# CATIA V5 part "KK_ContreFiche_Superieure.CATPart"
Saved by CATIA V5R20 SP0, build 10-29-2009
Part number: Contre fiche superieure
Bounding box of the stored display mesh (mm): x -2149.211 to -734.695, y 594.809 to 1312.939, z -1095.218 to -192.003
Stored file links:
  G:\Khaled_CFAO_2011\ST2M\ST2M_GR2\aboulegue\Khaled\CAD_thinkMOTION\KK_ContreFiche_Superieure.CATPart
  G:\Khaled_CFAO_2011\ST2M\ST2M_GR2\aboulegue\Khaled\CAD_thinkMOTION\KK_Train_Atterrissage.CATProduct
  G:\Khaled_CFAO_2011\ST2M\ST2M_GR2\aboulegue\CFAO_aboulegue\CFAO_aboulegue_fichiers_catia\Squelette_tige_verin_deverouillage.CATPart
  G:\Khaled_CFAO_2011\ST2M\ST2M_GR2\aboulegue\Khaled\CAD_thinkMOTION\KK_SqueletteContre_Friche.CATPart
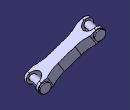
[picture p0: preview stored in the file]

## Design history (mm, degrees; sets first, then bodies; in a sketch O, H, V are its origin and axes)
External parameters (linked from other documents)
  `External.Longueur contre fiche superieure` = 1280 mm
Set1
  Plane1 "Plan reference contre fiche superieue": linked copy from another document
  Point1 "Point.15": linked copy from another document
  Point2 "Point.12": linked copy from another document
  Line1: linked copy from another document
  Point3 "Point.28": linked copy from another document
Body1 (main body)
  Sketch1 on Plane1, origin (95.3692, 652.5403, 0), H (0.9817, -0.1905, 0), V (0, 0, 1)
    construction line L1 (-2118.1492, -320) -> (-1013.8369, -967.2204)
    point P1 (-2118.1492, -320)
    point P2 (-1013.8369, -967.2204)
    line L2 (-2053.4272, -209.5688) -> (-949.1148, -856.7891)
    line L3 (-1078.5589, -1077.6516) -> (-2182.8713, -430.4312)
    arc A1 centre (-1013.8369, -967.2204) radius 128 from (-949.1148, -856.7891) to (-1078.5589, -1077.6516) cw
    arc A2 centre (-2118.1492, -320) radius 128 from (-2182.8713, -430.4312) to (-2053.4272, -209.5688) cw
    reference projected point E1 (-1013.8369, -967.2204) from Point1
    reference projected point E2 (-2118.1492, -320) from Point2
    distance L1 L2 = 128 {= 128mm*(`External.Longueur contre fiche superieure` /1280mm)}
    tangency: A1 L2, A2 L2, A1 L3, A2 L3
    coincidence: P2 E1, P1 E2
  Pad1: profile Sketch1, direction (-0.1905, -0.9817, 0), length 208 {= 208mm*(`External.Longueur contre fiche superieure` /1280mm)}, mirrored extent
  Sketch2 on face of Pad1 from Sketch1.L2, origin (-620.982, 92.7993, -1063.3821), H (0.1586, 0.9872, 0.0189), V (-0.8535, 0.1274, 0.5053)
    construction line L1 (9.8704, 1048.9435) -> (1379.4914, 997.579)
    reference projected line E1 (748.7259, 1661.2666) -> (700.7562, 382.1658) from Line1
    reference projected point E2 (724.7567, 1022.1333) from Point3
    point P3 (580.8578, 1027.5299)
    line L2 (580.8578, 1027.5299) -> (573.3626, 827.6704)
    arc A1 centre (-161.246, 855.2202) radius 735.125 from (573.3626, 827.6704) to (498.1646, 530.2797) cw
    line L3 (498.1646, 530.2797) -> (487.5214, 246.4792)
    line L4 (487.5214, 246.4792) -> (551.4764, 244.0807)
    point P8 (551.4764, 244.0807)
    line L5 (551.4764, 244.0807) -> (556.2734, 371.9908)
    arc A2 centre (712.6634, 366.1257) radius 156.5 from (556.2734, 371.9908) to (706.0185, 522.4846) cw
    line L6 (706.0185, 522.4846) -> (724.7567, 1022.1333)
    point P12 (724.7567, 1022.1333)
    line L7 (724.7567, 1022.1333) -> (580.8578, 1027.5299)
    axis line L8 (743.7009, 1527.2771) -> (710.9225, 653.2487)
    reference projected line E3 (748.7259, 1661.2666) -> (700.7562, 382.1658) from Line1
    reference projected line E4 (748.7259, 1661.2666) -> (700.7562, 382.1658) from Line1
    reference projected line E5 (748.7259, 1661.2666) -> (700.7562, 382.1658) from Line1
    reference projected line E6 (748.7259, 1661.2666) -> (700.7562, 382.1658) from Line1
    length L5 = 128
    length L7 = 144
    length L6 = 500
    distance L6 L3 = 208
    distance L4 L7 = 784 {= (`External.Longueur contre fiche superieure` /2)+144mm}
    length L3 = 284 {= (`External.Longueur contre fiche superieure` /2)+144mm-500mm}
    length L2 = 200
    perpendicularity: E1 L1
    coincidence: E2 L1, P3 L1, P8 L2, P12 L1, E3 L8, L6 E6
    tangency: A1 L2, L5 A1, A2 L5
    parallelism: E4 L2, E5 L3, L4 L7
  Pocket1: profile Sketch2, direction (-0.4964, 0.0963, -0.8627), through (limit type 3), outer side
  Sketch3 on end face of Pad1, origin (64.6313, 446.6252, 0), H (0.9817, -0.1905, 0), V (0, 0, 1)
    circle A1 centre (-1022.8839, -967.2204) radius 80
    reference projected arc E1 centre (-1022.8839, -967.2204) radius 128 from (-1087.9657, -1077.44) to (-957.8021, -857.0008) ccw from edge [face of Pad1 from Sketch1.A1 | end face of Pad1]
    radius A1 = 80
    concentricity: A1 E1
  Pocket2: profile Sketch3, direction (0.1905, 0.9817, 0), through (limit type 3)
  Mirror1: of the body so far, about face of Pocket1 from Sketch2.L6
  Mirror2: of the body so far, about face of Pocket1
  Sketch4 on face of Mirror1, origin (126.1072, 858.4554, 0), H (-0.9817, 0.1905, 0), V (0, 0, 1)
    circle A1 centre (1004.7898, -967.2204) radius 112
    point P1 (1004.7898, -967.2204)
    reference projected point E1 (1004.7898, -967.2204) from Point1
    radius A1 = 112 {= (224mm/2)*(`External.Longueur contre fiche superieure` /1280mm)}
    coincidence: E1 P1
  Pad2: profile Sketch4, direction (0.1905, 0.9817, 0), length 32 {= 32mm*(`External.Longueur contre fiche superieure` /1280mm)}
  Sketch5 on start face of Pad2, origin (126.1072, 858.4554, 0), H (0.9817, -0.1905, 0), V (0, 0, 1)
    circle A1 centre (-1004.7898, -967.2204) radius 80
    reference projected circle E1 centre (-1004.7898, -967.2204) radius 80 from edge [face of Mirror1 | start face of Pad2]
    coincidence: E1 A1
  Pad3: profile Sketch5, direction (-0.1905, -0.9817, 0), length 448
  Sketch6 on face of Mirror2, origin (126.1072, 858.4554, 0), H (-0.9817, 0.1905, 0), V (0, 0, 1)
    circle A1 centre (2109.1022, -320) radius 112
    reference projected arc E1 centre (2109.1022, -320) radius 128 from (2174.184, -430.2196) to (2044.0204, -209.7804) ccw from edge [face of Mirror2 | face of Mirror2]
    radius A1 = 112 {= (224mm/2)*(`External.Longueur contre fiche superieure` /1280mm)}
    concentricity: A1 E1
  Pad4: profile Sketch6, direction (0.1905, 0.9817, 0), length 32 {= 32mm*(`External.Longueur contre fiche superieure` /1280mm)}
  Sketch7 on start face of Pad4, origin (126.1072, 858.4554, 0), H (0.9817, -0.1905, 0), V (0, 0, 1)
    circle A1 centre (-2109.1022, -320) radius 80
    reference projected circle E1 centre (-2109.1022, -320) radius 80 from edge [start face of Pad4 | face of Mirror2]
    coincidence: A1 E1
  Pad5: profile Sketch7, direction (-0.1905, -0.9817, 0), length 448 {= 448mm*(`External.Longueur contre fiche superieure` /1280mm)}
